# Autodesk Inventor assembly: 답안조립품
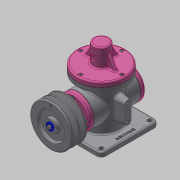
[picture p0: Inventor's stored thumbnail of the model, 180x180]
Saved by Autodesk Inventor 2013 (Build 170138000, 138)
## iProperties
Created: 2020-02
Part Number: 답안조립품
Document SubType Name: Assembly
Designer: Administrator
Author: Administrator
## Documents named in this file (21)
- C:\Users\Administrator\Desktop\600206V1020\답안조립품.iam
- C:\Users\Administrator\Desktop\600206V1020\본체.ipt
- C:\Users\Administrator\Desktop\600206V1020\E-링.ipt
- C:\Users\Administrator\Desktop\600206V1020\V-벨트풀리.ipt
- C:\Users\Administrator\Desktop\600206V1020\가변스프링.ipt
- C:\Users\Administrator\Desktop\600206V1020\개스킷 A.ipt
- C:\Users\Administrator\Desktop\600206V1020\개스킷 B.ipt
- C:\Users\Administrator\Desktop\600206V1020\덮개.ipt
- C:\Users\Administrator\Desktop\600206V1020\뒤커버.ipt
- C:\Users\Administrator\Desktop\600206V1020\링크.ipt
- C:\Users\Administrator\Desktop\600206V1020\베어링 17 x 40 x 12.ipt
- C:\Users\Administrator\Desktop\600206V1020\볼트 M4 x 10.ipt
- C:\Users\Administrator\Desktop\600206V1020\슬라이더.ipt
- C:\Users\Administrator\Desktop\600206V1020\앞커버.ipt
- C:\Users\Administrator\Desktop\600206V1020\오일 실 17 30 8.ipt
- C:\Users\Administrator\Desktop\600206V1020\와셔 4x16.ipt
- C:\Users\Administrator\Desktop\600206V1020\육각 소켓 머리 볼트 M4 x 10.ipt
- C:\Users\Administrator\Desktop\600206V1020\클레비스 핀 6 x 22.ipt
- 클레비스 핀 6 x 22.ipt
- C:\Users\Administrator\Desktop\600206V1020\키 4 x 4 x 25.ipt
- C:\Users\Administrator\Desktop\600206V1020\편심축.ipt
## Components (6 placed, 5 different names)
1. E-링:1
2. V-벨트풀리:1
3. 가변스프링:1
4. 개스킷 A:1
5. 개스킷 B:1
6. 개스킷 A:2
